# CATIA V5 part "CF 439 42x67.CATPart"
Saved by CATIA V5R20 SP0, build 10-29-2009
Part number: CF 439 42x67
Definition: NONE
Nomenclature: CF 439 42x67
Source: Unknown
Description: CF 439 42x67
Bounding box of the stored display mesh (mm): x -31.5 to 31.5, y 0 to 67, z -31.5 to 31.5
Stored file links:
  C:\Users\Utente\Desktop\IO LAVORO\3D X SITO CF\X SITO\CF 439\CF 439 42x67.CATPart
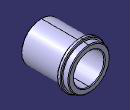
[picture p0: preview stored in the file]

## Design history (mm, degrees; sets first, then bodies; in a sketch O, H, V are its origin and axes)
Body1 "CF 439 42x67" (main body)
  Solid1: solid without history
